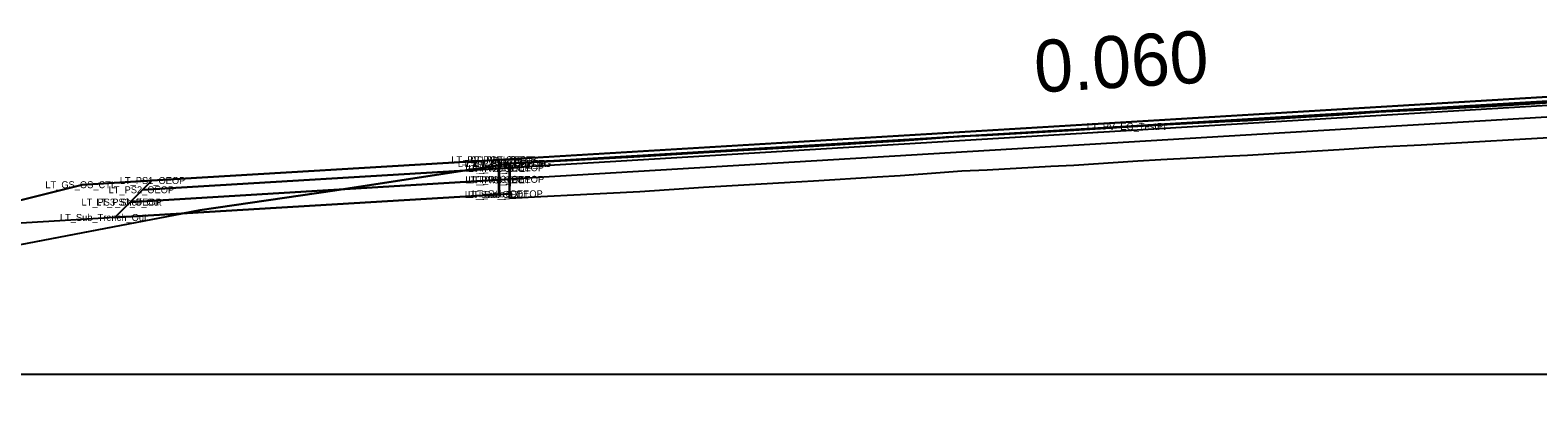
# Model space of a CAD drawing. Extents: x 2177029 to 2201446, y 59897 to 78390.
# Drawn here: x 2200162.97 to 2200206.38, y 64406.43 to 64417.22 of the extents above; entities that cross this region are included whole.
import ezdxf

# ---------------------------------------------------------------- set-up
doc = ezdxf.new("R2010")
doc.units = 0
for name, color, linetype in [('Exist Cross Section Cell', 7, 'Continuous'), ('Exist PHM Roadway Shape', 7, 'Continuous'), ('Exist XS Ground Line', 7, 'Continuous'), ('Old_Level_11', 7, 'Continuous'), ('Prop CMT Conc Surface', 7, 'Continuous'), ('Prop CMT Concrete Structures', 7, 'Continuous'), ('Prop CMT Guardrail Graphics', 7, 'Continuous'), ('Prop CMT Pvmt Course 1 CG', 7, 'Continuous'), ('Prop CMT Pvmt Course 2', 7, 'Continuous'), ('Prop CMT Pvmt Course 2 CG', 7, 'Continuous'), ('Prop CMT Pvmt Course 3', 7, 'Continuous'), ('Prop CMT Pvmt Course 4', 7, 'Continuous'), ('Prop CMT Pvmt Surface', 7, 'Continuous'), ('Prop CMT Pvmt Wedge Surface 1', 7, 'Continuous'), ('Prop CMT Slope Grass', 7, 'Continuous'), ('Prop CMT Subgrade Earthwork', 7, 'Continuous'), ('Prop Hatching', 7, 'Continuous'), ('Prop XS Side Slope Text', 7, 'Continuous'), ('Scratch_Level_0', 7, 'Continuous'), ('Scratch_Level_9', 7, 'Continuous')]:
    doc.layers.add(name, color=color, linetype=linetype)

msp = doc.modelspace()

# ---------------------------------------------------------------- linework, layer by layer
at = {"layer": 'Exist Cross Section Cell'}
msp.add_line((2200042.732, 64407.31), (2200242.732, 64407.31), dxfattribs=at)
at = {"layer": 'Exist XS Ground Line'}
msp.add_lwpolyline([(2200161.772, 64410.874), (2200167.852, 64412.04), (2200171.735, 64412.6), (2200176.769, 64413.382), (2200177.672, 64413.433), (2200178.053, 64413.453), (2200178.429, 64413.472), (2200180.523, 64413.579), (2200182.353, 64413.697), (2200183.022, 64413.738), (2200184.856, 64413.84), (2200185.523, 64413.878), (2200187.357, 64413.998), (2200188.023, 64414.039), (2200188.667, 64414.087), (2200189.792, 64414.171), (2200190.523, 64414.2), (2200192.361, 64414.302), (2200193.022, 64414.338), (2200194.862, 64414.457), (2200195.522, 64414.499), (2200197.364, 64414.592), (2200198.022, 64414.625), (2200199.866, 64414.735), (2200200.659, 64414.784), (2200201.806, 64414.866), (2200203.023, 64414.924), (2200204.869, 64415.027), (2200205.523, 64415.063), (2200207.371, 64415.173)], dxfattribs=at)
at = {"layer": 'Prop CMT Conc Surface'}
for points in [[(2200212.732, 64415.542), (2200176.769, 64413.384)], [(2200176.476, 64413.242), (2200176.476, 64413.492)], [(2200176.769, 64413.259), (2200176.476, 64413.242)], [(2200176.769, 64413.384), (2200176.769, 64413.259)]]:
    msp.add_lwpolyline(points, dxfattribs=at)
at = {"layer": 'Prop CMT Concrete Structures'}
for p, q in [((2200212.732, 64415.667), (2200176.476, 64413.492)), ((2200176.476, 64413.492), (2200176.466, 64413.491))]:
    msp.add_line(p, q, dxfattribs=at)
at = {"layer": 'Prop CMT Guardrail Graphics'}
for points in [[(2200212.732, 64415.084), (2200176.476, 64412.908)], [(2200176.476, 64412.908), (2200176.476, 64413.492)]]:
    msp.add_lwpolyline(points, dxfattribs=at)
at = {"layer": 'Prop CMT Pvmt Course 1 CG'}
for points in [[(2200176.466, 64412.908), (2200165.846, 64412.27)], [(2200176.466, 64412.491), (2200176.466, 64412.908)], [(2200165.402, 64411.827), (2200176.466, 64412.491)], [(2200165.846, 64412.27), (2200165.402, 64411.827)], [(2200165.846, 64412.27), (2200165.846, 64412.27)]]:
    msp.add_lwpolyline(points, dxfattribs=at)
at = {"layer": 'Prop CMT Pvmt Course 2'}
for points in [[(2200176.476, 64412.908), (2200176.466, 64412.908)], [(2200176.466, 64412.908), (2200176.466, 64412.491)], [(2200176.769, 64412.926), (2200176.476, 64412.908)], [(2200176.476, 64412.492), (2200176.476, 64412.908)], [(2200176.476, 64412.908), (2200176.476, 64412.492)], [(2200176.769, 64412.509), (2200176.769, 64412.926)], [(2200176.466, 64412.491), (2200176.476, 64412.492)], [(2200176.476, 64412.492), (2200176.769, 64412.509)]]:
    msp.add_lwpolyline(points, dxfattribs=at)
at = {"layer": 'Prop CMT Pvmt Course 2 CG'}
for points in [[(2200212.732, 64415.667), (2200176.476, 64413.492)], [(2200176.769, 64413.384), (2200212.732, 64415.542)], [(2200176.476, 64413.492), (2200176.468, 64413.491), (2200176.466, 64413.491)], [(2200176.466, 64413.491), (2200176.466, 64413.241)], [(2200176.466, 64413.241), (2200176.476, 64413.242)], [(2200176.476, 64413.242), (2200176.476, 64413.492)], [(2200176.476, 64413.492), (2200176.476, 64413.242)], [(2200176.476, 64413.242), (2200176.769, 64413.259)], [(2200176.769, 64413.259), (2200176.769, 64413.384)]]:
    msp.add_lwpolyline(points, dxfattribs=at)
at = {"layer": 'Prop CMT Pvmt Course 3'}
for points in [[(2200176.769, 64412.509), (2200176.784, 64413.382)], [(2200176.466, 64412.491), (2200165.402, 64411.827)], [(2200176.476, 64412.492), (2200176.466, 64412.491)], [(2200176.769, 64412.509), (2200176.476, 64412.492)], [(2200165.402, 64411.827), (2200159.203, 64411.455)]]:
    msp.add_lwpolyline(points, dxfattribs=at)
at = {"layer": 'Prop CMT Pvmt Course 4'}
msp.add_lwpolyline([(2200176.466, 64413.491), (2200166.466, 64412.891)], dxfattribs=at)
at = {"layer": 'Prop CMT Pvmt Surface'}
for points in [[(2200212.732, 64415.436), (2200212.374, 64415.42), (2200210.522, 64415.331), (2200209.873, 64415.301), (2200208.022, 64415.212), (2200207.371, 64415.173), (2200205.523, 64415.063), (2200204.869, 64415.027), (2200203.023, 64414.924), (2200202.887, 64414.919), (2200201.806, 64414.866), (2200200.659, 64414.784), (2200200.523, 64414.774), (2200199.866, 64414.735), (2200198.022, 64414.625), (2200197.364, 64414.592), (2200195.522, 64414.499), (2200194.862, 64414.457), (2200193.022, 64414.338), (2200192.361, 64414.302), (2200190.523, 64414.2), (2200190.264, 64414.19), (2200190.04, 64414.181)], [(2200190.264, 64414.194), (2200190.523, 64414.21), (2200192.361, 64414.32), (2200193.022, 64414.36), (2200194.862, 64414.47), (2200195.522, 64414.51), (2200197.364, 64414.62), (2200198.022, 64414.66), (2200199.866, 64414.77), (2200200.523, 64414.81), (2200200.659, 64414.818), (2200201.806, 64414.887), (2200202.887, 64414.952), (2200203.023, 64414.96), (2200204.869, 64415.071), (2200205.523, 64415.11), (2200207.371, 64415.221), (2200208.022, 64415.26), (2200209.873, 64415.371), (2200210.522, 64415.41), (2200212.374, 64415.521), (2200212.732, 64415.542)], [(2200176.769, 64413.384), (2200176.769, 64413.384), (2200177.548, 64413.431), (2200177.672, 64413.439), (2200178.053, 64413.461), (2200178.429, 64413.484), (2200180.523, 64413.61), (2200182.353, 64413.72), (2200183.022, 64413.76), (2200184.856, 64413.87), (2200185.523, 64413.91), (2200187.357, 64414.02), (2200188.023, 64414.06), (2200188.667, 64414.098), (2200189.455, 64414.146)], [(2200189.455, 64414.146), (2200188.667, 64414.087), (2200188.023, 64414.039), (2200187.357, 64413.998), (2200185.523, 64413.878), (2200184.856, 64413.84), (2200183.022, 64413.738), (2200182.353, 64413.697), (2200180.523, 64413.579), (2200178.429, 64413.472), (2200178.053, 64413.453), (2200177.672, 64413.433), (2200177.548, 64413.425), (2200176.769, 64413.382), (2200176.769, 64413.382)], [(2200190.04, 64414.181), (2200190.264, 64414.194)], [(2200176.769, 64413.382), (2200176.769, 64413.384)]]:
    msp.add_lwpolyline(points, dxfattribs=at)
at = {"layer": 'Prop CMT Pvmt Wedge Surface 1'}
for p, q in [((2200205.523, 64414.063), (2200207.371, 64414.173)), ((2200198.022, 64413.625), (2200199.866, 64413.735)), ((2200199.866, 64413.735), (2200200.659, 64413.784)), ((2200200.659, 64413.784), (2200201.806, 64413.866)), ((2200201.806, 64413.866), (2200203.023, 64413.924)), ((2200203.023, 64413.924), (2200204.869, 64414.027)), ((2200204.869, 64414.027), (2200205.523, 64414.063)), ((2200176.769, 64412.382), (2200176.769, 64413.382)), ((2200190.523, 64413.2), (2200192.361, 64413.302)), ((2200192.361, 64413.302), (2200193.022, 64413.338)), ((2200193.022, 64413.338), (2200194.862, 64413.457)), ((2200194.862, 64413.457), (2200195.522, 64413.499)), ((2200195.522, 64413.499), (2200197.364, 64413.592)), ((2200197.364, 64413.592), (2200198.022, 64413.625)), ((2200183.022, 64412.738), (2200184.856, 64412.84)), ((2200184.856, 64412.84), (2200185.523, 64412.878)), ((2200185.523, 64412.878), (2200187.357, 64412.998)), ((2200187.357, 64412.998), (2200188.023, 64413.039)), ((2200188.023, 64413.039), (2200188.667, 64413.087)), ((2200188.667, 64413.087), (2200189.792, 64413.171)), ((2200189.792, 64413.171), (2200190.523, 64413.2)), ((2200176.769, 64412.382), (2200177.672, 64412.433)), ((2200177.672, 64412.433), (2200178.053, 64412.453)), ((2200178.053, 64412.453), (2200178.429, 64412.472)), ((2200178.429, 64412.472), (2200180.523, 64412.579)), ((2200180.523, 64412.579), (2200182.353, 64412.697)), ((2200182.353, 64412.697), (2200183.022, 64412.738))]:
    msp.add_line(p, q, dxfattribs=at)
at = {"layer": 'Prop CMT Slope Grass'}
for points in [[(2200176.476, 64413.242), (2200176.466, 64413.241)], [(2200176.466, 64413.241), (2200176.466, 64412.908)], [(2200176.769, 64413.259), (2200176.476, 64413.242)], [(2200176.476, 64412.908), (2200176.476, 64413.242)], [(2200176.476, 64413.242), (2200176.476, 64412.908)], [(2200176.769, 64412.926), (2200176.769, 64413.259)], [(2200176.466, 64412.908), (2200176.476, 64412.908)], [(2200176.476, 64412.908), (2200176.769, 64412.926)]]:
    msp.add_lwpolyline(points, dxfattribs=at)
at = {"layer": 'Prop CMT Subgrade Earthwork'}
for points in [[(2200212.732, 64415.417), (2200176.476, 64413.242)], [(2200176.476, 64413.242), (2200176.476, 64413.492)]]:
    msp.add_lwpolyline(points, dxfattribs=at)
at = {"layer": 'Prop Hatching'}
msp.add_lwpolyline([(2200166.466, 64412.891), (2200164.466, 64412.771), (2200139.102, 64406.43)], dxfattribs=at)
at = {"layer": 'Prop XS Side Slope Text'}
msp.add_lwpolyline([(2200207.371, 64415.173), (2200205.523, 64415.063), (2200204.869, 64415.027), (2200203.023, 64414.924), (2200201.806, 64414.866), (2200200.659, 64414.784), (2200199.866, 64414.735), (2200198.022, 64414.625), (2200197.364, 64414.592), (2200195.522, 64414.499), (2200194.862, 64414.457), (2200193.022, 64414.338), (2200192.361, 64414.302), (2200190.523, 64414.2), (2200189.792, 64414.171), (2200188.667, 64414.087), (2200188.023, 64414.039), (2200187.357, 64413.998), (2200185.523, 64413.878), (2200184.856, 64413.84), (2200183.022, 64413.738), (2200182.353, 64413.697), (2200180.523, 64413.579), (2200178.429, 64413.472), (2200178.053, 64413.453), (2200177.672, 64413.433), (2200176.784, 64413.382), (2200171.735, 64412.6), (2200167.852, 64412.04), (2200167.352, 64411.944), (2200165.402, 64411.827), (2200159.202, 64411.455), (2200164.466, 64412.771), (2200166.466, 64412.891), (2200176.466, 64413.491), (2200212.732, 64415.667)], dxfattribs=at)
for points in [[(2200176.769, 64412.509), (2200176.476, 64412.492), (2200167.352, 64411.944), (2200167.852, 64412.04), (2200171.735, 64412.6), (2200176.784, 64413.382)], [(2200165.402, 64411.827), (2200159.202, 64411.455), (2200148.877, 64408.874), (2200151.028, 64408.798), (2200161.772, 64410.874), (2200167.352, 64411.944)]]:
    msp.add_lwpolyline(points, close=True, dxfattribs=at)
at = {"layer": 'Scratch_Level_0'}
for points in [[(2200176.466, 64413.241), (2200166.201, 64412.625), (2200165.846, 64412.27)], [(2200176.466, 64412.908), (2200176.466, 64413.241)], [(2200165.846, 64412.27), (2200176.466, 64412.908)]]:
    msp.add_lwpolyline(points, dxfattribs=at)
at = {"layer": 'Scratch_Level_9'}
for points in [[(2200176.466, 64413.491), (2200166.466, 64412.891), (2200166.201, 64412.625)], [(2200166.201, 64412.625), (2200176.466, 64413.241)], [(2200176.466, 64413.241), (2200176.466, 64413.491)]]:
    msp.add_lwpolyline(points, dxfattribs=at)

# ---------------------------------------------------------------- texts
at = {"layer": 'Exist PHM Roadway Shape'}
for s, p in [('LT_PV_EG_TestPt', (2200193.392, 64414.349)), ('LT_PV1_OTL SE LB', (2200175.091, 64413.391)), ('LT_PV_Sub_Tie_Out', (2200175.279, 64413.282)), ('LT_PV2_OEOT', (2200175.494, 64413.142)), ('LT_PV_OEEOP_EG', (2200175.523, 64413.282)), ('LT_PV1_OEOT', (2200175.55, 64413.392)), ('LT_PV2_OTL', (2200175.581, 64413.141)), ('LT_PV1_OTL', (2200175.638, 64413.391)), ('LT_PV2_OEEOP', (2200175.699, 64413.159)), ('LT_PV1_OEEOP', (2200175.756, 64413.284)), ('LT_GS_OS_CTL', (2200163.403, 64412.671)), ('LT_PS1_OEOP', (2200165.546, 64412.791)), ('LT_PV3_OEOT', (2200175.494, 64412.808)), ('LT_PV3_OTL', (2200175.581, 64412.808)), ('LT_PV3_OEEOP', (2200175.699, 64412.826)), ('LT_PS3_Shelf_Out', (2200164.444, 64412.17)), ('LT_PS3_OEOP', (2200164.869, 64412.17)), ('LT_PS2_OEOP', (2200165.224, 64412.525)), ('LT_Sub_OEOT', (2200175.484, 64412.392)), ('LT_Sub_OTL', (2200175.572, 64412.391)), ('LT_Sub_OEEOP', (2200175.69, 64412.409)), ('LT_Sub_Trench_Out', (2200163.822, 64411.727))]:
    msp.add_text(s, height=0.2, dxfattribs=at).set_placement(p)
at = {"layer": 'Old_Level_11'}
msp.add_text('0.060', height=1.5, rotation=3.4331, dxfattribs=at).set_placement((2200191.924, 64415.421))

doc.saveas('drawing.dxf')
